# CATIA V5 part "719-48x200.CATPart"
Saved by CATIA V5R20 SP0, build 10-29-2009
Part number: 719-48x200
Definition: NONE
Nomenclature: 719-48x200
Source: Unknown
Description: 719-48x200
Bounding box of the stored display mesh (mm): x 0 to 247, y -31.5 to 31.5, z -31.5 to 31.5
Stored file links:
  C:\Users\Utente\Desktop\IO LAVORO\3D X SITO CF\X SITO\719\719-48x200.CATPart

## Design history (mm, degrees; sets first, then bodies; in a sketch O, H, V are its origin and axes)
Body1 "719-48x200" (main body)
  Solid1: solid without history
